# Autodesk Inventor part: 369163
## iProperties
Created: 2006-08
Part Number: 369163
Material: C45K
Description: Paßfeder
Vendor: Autodesk Inc.
Document SubType Name: Modeling
Standard: DIN 6885
Designer: I.Baliuc
Standards Organization: DIN
Language: de-DE
Size Designation: A 6 x 6 x 60
Categories: <MemberInstance Version="R10.0.0"><Categories><Category DisplayName="Wellenteile" InternalName="7f7aeb1f-a693-4053-b835-cee3144e0d98" Mnemonic="SHFT"><Category
Density: 7.85 g/cm^3
Mass: 16.5921 g
Surface Area: 14.6565 cm^2
Volume: 2.11365 cm^3
Abmessung: A 6 x 6 x 60
Author: T.Messerschmitt
Comments: DIN 6885 - A 6 x 6 x 60
Revision Number: 369163
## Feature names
1. Körper1 [Extrusion]
